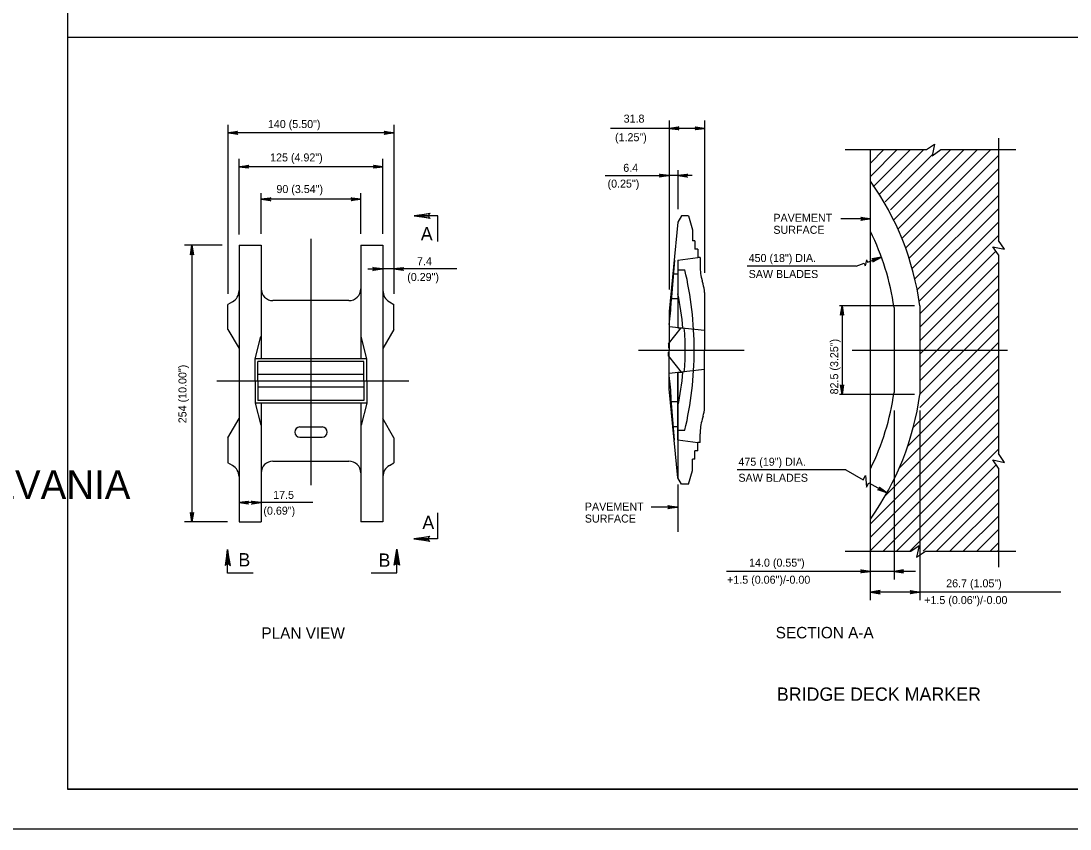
# Model space of a CAD drawing. Extents: x 639362 to 641108, y 298458 to 299646.
# Drawn here: x 640225.9 to 640619.2, y 298457.6 to 298760.6 of the extents above; entities that cross this region are included whole.
import ezdxf

# ---------------------------------------------------------------- set-up
doc = ezdxf.new("R2010")
doc.units = 0
for name, color, linetype in [('1', 7, 'Continuous'), ('2', 7, 'Continuous'), ('3', 7, 'Continuous'), ('PLT-BNDY', 7, 'Continuous')]:
    doc.layers.add(name, color=color, linetype=linetype)

# ---------------------------------------------------------------- blocks, each defined once
blk = doc.blocks.new('RARROW')
at = {"layer": '3'}
blk.add_lwpolyline([(-2.2695, 0.285), (-2.184875, 0.12075), (0, 0), (-2.2695, 0.285), (-2.38575, 0.384625), (0, 0), (-2.183125, -0.108), (-2.262875, -0.2705), (0, 0), (-2.38575, -0.379125), (-2.262875, -0.2705)], dxfattribs=at)

msp = doc.modelspace()

# ---------------------------------------------------------------- linework, layer by layer
at = {"layer": '1'}
for p, q in [((640243.31, 299036.63), (640243.31, 298472.63)), ((640243.31, 298754.63), (640829.31, 298754.63)), ((641029.31, 298472.63), (640243.31, 298472.63)), ((640243.31, 298472.63), (640829.31, 298472.63))]:
    msp.add_line(p, q, dxfattribs=at)
at = {"layer": '2'}
for p, q in [((640468.92, 298723.36), (640468.92, 298659.92)), ((640482.21, 298723.36), (640482.21, 298666.21)), ((640303.46, 298721.7), (640303.46, 298658.32)), ((640365.72, 298718.7), (640303.46, 298718.7)), ((640365.72, 298721.7), (640365.72, 298658.32)), ((640482.21, 298720.36), (640446.94, 298720.36)), ((640592.33, 298716.72), (640592.33, 298678.38)), ((640534.93, 298712.39), (640565.36, 298712.39)), ((640544.39, 298712.38), (640544.41, 298712.39)), ((640544.39, 298707.37), (640549.41, 298712.39)), ((640544.39, 298702.36), (640554.42, 298712.39)), ((640544.39, 298543.43), (640544.39, 298712.39)), ((640545.44, 298698.39), (640559.43, 298712.39)), ((640547.68, 298695.63), (640564.44, 298712.39)), ((640551.84, 298689.77), (640574.46, 298712.39)), ((640553.08, 298686), (640579.47, 298712.39)), ((640554.68, 298682.59), (640584.48, 298712.39)), ((640556.17, 298679.08), (640589.48, 298712.39)), ((640565.36, 298712.39), (640568.44, 298714.44)), ((640568.44, 298714.44), (640567.53, 298710.04)), ((640567.53, 298710.04), (640570.82, 298712.39)), ((640570.82, 298712.39), (640598.86, 298712.39)), ((640307.61, 298680.52), (640307.61, 298708.97)), ((640361.56, 298680.82), (640361.56, 298708.97)), ((640549.92, 298692.86), (640567.64, 298710.58)), ((640557.56, 298675.46), (640592.33, 298710.23)), ((640361.56, 298705.97), (640307.61, 298705.97)), ((640472.14, 298704.67), (640472.14, 298690.08)), ((640558.84, 298671.73), (640592.33, 298705.22)), ((640444.93, 298702.66), (640468.92, 298702.66)), ((640477.55, 298702.66), (640468.92, 298702.66)), ((640560, 298667.88), (640592.33, 298700.21)), ((640315.91, 298680.82), (640315.91, 298696.07)), ((640353.26, 298680.82), (640353.26, 298696.07)), ((640561.03, 298663.91), (640592.33, 298695.2)), ((640353.26, 298693.8), (640315.91, 298693.8)), ((640382.2, 298687.58), (640373.32, 298687.58)), ((640382.2, 298677.95), (640382.2, 298687.58)), ((640473.47, 298687.55), (640472.14, 298685.17)), ((640476.19, 298687.55), (640473.47, 298687.55)), ((640476.19, 298687.55), (640477.59, 298682.33)), ((640561.93, 298659.79), (640592.33, 298690.19)), ((640472.14, 298685.17), (640468.92, 298651.74)), ((640544.39, 298686.43), (640533.26, 298686.43)), ((640562.68, 298655.53), (640592.33, 298685.18)), ((640477.59, 298682.33), (640477.59, 298678.19)), ((640562.92, 298650.77), (640592.33, 298680.18)), ((640301.31, 298676.52), (640287.16, 298676.52)), ((640289.95, 298676.52), (640289.95, 298572.76)), ((640307.61, 298676.52), (640307.61, 298572.76)), ((640307.61, 298676.52), (640315.91, 298676.52)), ((640315.91, 298676.52), (640315.91, 298633.98)), ((640334.59, 298678.97), (640334.59, 298586.59)), ((640353.26, 298676.52), (640361.56, 298676.52)), ((640353.26, 298676.52), (640353.26, 298633.98)), ((640361.56, 298676.52), (640361.56, 298572.76)), ((640478.57, 298678.17), (640477.7, 298678.19)), ((640478.57, 298678.17), (640478.57, 298675.06)), ((640592.33, 298672.91), (640590.28, 298675.99)), ((640590.28, 298675.99), (640594.68, 298675.09)), ((640594.68, 298675.09), (640592.33, 298678.38)), ((640472.14, 298670.91), (640479.64, 298671.93)), ((640479.64, 298675.04), (640478.57, 298675.06)), ((640479.64, 298675.04), (640479.64, 298671.93)), ((640480.51, 298671.91), (640479.64, 298671.93)), ((640480.51, 298671.91), (640480.51, 298668.68)), ((640543.21, 298670.21), (640548.48, 298672.12)), ((640562.92, 298645.76), (640591.43, 298674.27)), ((640592.33, 298672.91), (640592.33, 298598.42)), ((640355.97, 298667.66), (640361.4, 298667.66)), ((640365.72, 298667.66), (640361.64, 298667.66)), ((640389.26, 298667.66), (640365.72, 298667.66)), ((640470.85, 298670.98), (640469.68, 298655.59)), ((640472.14, 298670.91), (640472.14, 298645.64)), ((640538.96, 298668.66), (640498.21, 298668.66)), ((640538.96, 298668.66), (640542.03, 298669.78)), ((640542.03, 298669.78), (640542.37, 298668.84)), ((640542.88, 298671.12), (640542.37, 298668.84)), ((640542.88, 298671.12), (640543.21, 298670.21)), ((640562.92, 298640.75), (640592.33, 298670.16)), ((640470.46, 298665.86), (640472.14, 298665.86)), ((640472.14, 298667.32), (640474.77, 298667.32)), ((640562.92, 298635.74), (640592.33, 298665.15)), ((640481.61, 298662.05), (640481.29, 298663.16)), ((640562.92, 298630.73), (640592.33, 298660.14)), ((640348.84, 298655.77), (640320.34, 298655.77)), ((640469.68, 298656.51), (640472.14, 298656.51)), ((640482.14, 298658.81), (640482.14, 298637.23)), ((640305.17, 298655.31), (640303.46, 298654.32)), ((640303.46, 298644.96), (640303.46, 298654.32)), ((640364, 298655.31), (640365.72, 298654.32)), ((640365.72, 298644.96), (640365.72, 298654.32)), ((640468.92, 298651.74), (640468.92, 298637.23)), ((640560.92, 298653.87), (640532.71, 298653.87)), ((640533.71, 298653.87), (640533.71, 298620.58)), ((640553.25, 298653.19), (640553.25, 298621.27)), ((640562.92, 298625.73), (640592.33, 298655.13)), ((640562.92, 298653.87), (640562.92, 298620.58)), ((640562.92, 298620.72), (640592.33, 298650.12)), ((640303.46, 298644.96), (640307.61, 298637.77)), ((640365.72, 298644.96), (640361.56, 298637.77)), ((640468.65, 298639.55), (640473.41, 298645.55)), ((640482.14, 298644.53), (640468.92, 298645.97)), ((640472.14, 298645.53), (640473.69, 298645.53)), ((640562.92, 298615.71), (640592.33, 298645.11)), ((640313.66, 298633.98), (640315.77, 298642.33)), ((640355.51, 298633.98), (640353.4, 298642.33)), ((640560.45, 298608.23), (640592.33, 298640.1)), ((640457.4, 298637.23), (640496.99, 298637.23)), ((640468.65, 298639.55), (640468.65, 298637.97)), ((640468.65, 298634.9), (640468.65, 298636.49)), ((640468.92, 298622.71), (640468.92, 298637.23)), ((640482.14, 298615.64), (640482.14, 298637.23)), ((640537.51, 298637.23), (640595.72, 298637.23)), ((640355.51, 298633.98), (640313.66, 298633.98)), ((640313.66, 298625.68), (640313.66, 298633.98)), ((640314.72, 298625.68), (640314.72, 298632.99)), ((640354.46, 298632.99), (640314.72, 298632.99)), ((640354.46, 298625.68), (640354.46, 298632.99)), ((640355.51, 298625.68), (640355.51, 298633.98)), ((640468.65, 298634.9), (640473.41, 298628.91)), ((640558.29, 298601.06), (640592.33, 298635.1)), ((640482.14, 298629.92), (640468.92, 298628.48)), ((640472.14, 298628.93), (640473.69, 298628.93)), ((640472.14, 298628.81), (640472.14, 298589.29)), ((640472.14, 298603.55), (640472.14, 298628.81)), ((640555.13, 298592.89), (640592.33, 298630.09)), ((640299.32, 298625.68), (640371.31, 298625.68)), ((640313.66, 298625.68), (640313.66, 298617.38)), ((640354.46, 298628.01), (640314.72, 298628.01)), ((640314.72, 298625.68), (640314.72, 298618.38)), ((640354.46, 298625.68), (640354.46, 298618.38)), ((640355.51, 298625.68), (640355.51, 298617.38)), ((640550.12, 298582.87), (640592.33, 298625.08)), ((640354.46, 298623.36), (640314.72, 298623.36)), ((640472.14, 298589.29), (640468.92, 298622.71)), ((640560.92, 298620.58), (640532.71, 298620.58)), ((640355.51, 298617.38), (640313.66, 298617.38)), ((640313.66, 298617.38), (640315.77, 298609.04)), ((640354.46, 298618.38), (640314.72, 298618.38)), ((640315.91, 298617.38), (640315.91, 298572.76)), ((640353.26, 298617.38), (640353.26, 298572.76)), ((640355.51, 298617.38), (640353.4, 298609.04)), ((640470.85, 298603.47), (640469.68, 298618.86)), ((640469.68, 298617.94), (640472.14, 298617.94)), ((640544.39, 298572.13), (640592.33, 298620.07)), ((640481.61, 298612.41), (640481.29, 298611.29)), ((640544.39, 298567.13), (640592.33, 298615.06)), ((640553.25, 298614.58), (640553.25, 298551.25)), ((640562.92, 298614.58), (640562.92, 298543.43)), ((640303.46, 298604.32), (640307.61, 298611.52)), ((640330.41, 298608.39), (640338.77, 298608.39)), ((640365.72, 298604.32), (640361.56, 298611.52)), ((640470.46, 298608.59), (640472.14, 298608.59)), ((640544.39, 298562.12), (640592.33, 298610.05)), ((640330.41, 298604.58), (640338.77, 298604.58)), ((640472.14, 298607.14), (640474.77, 298607.14)), ((640480.51, 298602.55), (640480.51, 298605.78)), ((640549.15, 298561.86), (640592.33, 298605.04)), ((640303.46, 298604.32), (640303.46, 298594.97)), ((640365.72, 298604.32), (640365.72, 298594.97)), ((640472.14, 298603.55), (640479.64, 298602.53)), ((640480.51, 298602.55), (640479.64, 298602.53)), ((640479.64, 298599.42), (640479.64, 298602.53)), ((640479.64, 298599.42), (640478.57, 298599.4)), ((640478.57, 298596.29), (640478.57, 298599.4)), ((640554.15, 298561.86), (640592.33, 298600.04)), ((640594.68, 298595.13), (640592.33, 298598.42)), ((640305.17, 298593.98), (640303.46, 298594.97)), ((640320.34, 298595.59), (640348.84, 298595.59)), ((640364, 298593.98), (640365.72, 298594.97)), ((640477.59, 298592.12), (640477.59, 298596.27)), ((640478.57, 298596.29), (640477.7, 298596.27)), ((640559.16, 298561.86), (640591.5, 298594.2)), ((640592.33, 298592.95), (640590.28, 298596.03)), ((640590.28, 298596.03), (640594.68, 298595.13)), ((640592.33, 298592.95), (640592.33, 298555.85)), ((640473.47, 298586.9), (640472.14, 298589.29)), ((640476.19, 298586.9), (640477.59, 298592.12)), ((640535.12, 298592.27), (640494.36, 298592.27)), ((640535.12, 298592.27), (640541.64, 298588.63)), ((640541.64, 298588.63), (640542.49, 298590.16)), ((640542.49, 298590.16), (640542.86, 298585.81)), ((640564.17, 298561.86), (640592.33, 298590.02)), ((640472.14, 298586.8), (640472.14, 298569.08)), ((640476.19, 298586.9), (640473.47, 298586.9)), ((640542.86, 298585.81), (640543.77, 298587.45)), ((640543.77, 298587.45), (640550.57, 298583.67)), ((640569.18, 298561.86), (640592.33, 298585.01)), ((640315.91, 298580.01), (640307.61, 298580.01)), ((640335.34, 298580.01), (640315.91, 298580.01)), ((640472.04, 298578.32), (640462.16, 298578.32)), ((640574.19, 298561.86), (640592.33, 298580)), ((640382.08, 298576.2), (640382.08, 298566.45)), ((640579.2, 298561.86), (640592.33, 298574.99)), ((640303.31, 298572.76), (640287.16, 298572.76)), ((640307.61, 298572.76), (640315.91, 298572.76)), ((640361.56, 298572.76), (640353.26, 298572.76)), ((640584.21, 298561.86), (640592.33, 298569.98)), ((640382.08, 298566.45), (640373.2, 298566.45)), ((640303.35, 298553.53), (640303.35, 298562.4)), ((640366.8, 298553.68), (640366.8, 298562.56)), ((640534.93, 298561.86), (640559.51, 298561.86)), ((640559.51, 298561.86), (640562.59, 298563.91)), ((640562.59, 298563.91), (640561.68, 298559.51)), ((640561.68, 298559.51), (640564.97, 298561.86)), ((640564.97, 298561.86), (640598.86, 298561.86)), ((640589.21, 298561.86), (640592.33, 298564.98)), ((640591.97, 298561.86), (640592.33, 298562.18)), ((640312.97, 298553.53), (640303.35, 298553.53)), ((640357.17, 298553.68), (640366.8, 298553.68)), ((640553.25, 298554.25), (640490.35, 298554.25)), ((640561.32, 298554.25), (640553.25, 298554.25)), ((640562.92, 298546.43), (640544.39, 298546.43)), ((640615.75, 298546.43), (640562.92, 298546.43))]:
    msp.add_line(p, q, dxfattribs=at)
for points in [[(640306.86, 298718.27), (640306.74, 298718.52), (640303.46, 298718.7), (640306.86, 298718.27), (640307.04, 298718.12), (640303.46, 298718.7), (640306.73, 298718.86), (640306.85, 298719.1), (640303.46, 298718.7), (640307.04, 298719.27), (640306.85, 298719.1)], [(640362.31, 298719.12), (640362.44, 298718.88), (640365.72, 298718.7), (640362.31, 298719.12), (640362.14, 298719.27), (640365.72, 298718.7), (640362.44, 298718.53), (640362.32, 298718.29), (640365.72, 298718.7), (640362.14, 298718.13), (640362.32, 298718.29)], [(640472.32, 298719.93), (640472.2, 298720.18), (640468.92, 298720.36), (640472.32, 298719.93), (640472.5, 298719.78), (640468.92, 298720.36), (640472.19, 298720.52), (640472.31, 298720.76), (640468.92, 298720.36), (640472.5, 298720.93), (640472.31, 298720.76)], [(640478.8, 298720.79), (640478.93, 298720.54), (640482.21, 298720.36), (640478.8, 298720.79), (640478.63, 298720.93), (640482.21, 298720.36), (640478.93, 298720.19), (640478.81, 298719.95), (640482.21, 298720.36), (640478.63, 298719.79), (640478.81, 298719.95)], [(640311.01, 298705.54), (640310.89, 298705.79), (640307.61, 298705.97), (640311.01, 298705.54), (640311.19, 298705.39), (640307.61, 298705.97), (640310.88, 298706.13), (640311, 298706.38), (640307.61, 298705.97), (640311.19, 298706.54), (640311, 298706.38)], [(640358.16, 298706.4), (640358.29, 298706.15), (640361.56, 298705.97), (640358.16, 298706.4), (640357.98, 298706.54), (640361.56, 298705.97), (640358.29, 298705.81), (640358.17, 298705.56), (640361.56, 298705.97), (640357.98, 298705.4), (640358.17, 298705.56)], [(640465.51, 298703.09), (640465.64, 298702.85), (640468.92, 298702.66), (640465.51, 298703.09), (640465.34, 298703.24), (640468.92, 298702.66), (640465.64, 298702.5), (640465.52, 298702.26), (640468.92, 298702.66), (640465.34, 298702.1), (640465.52, 298702.26)], [(640475.55, 298702.23), (640475.42, 298702.48), (640472.14, 298702.66), (640475.55, 298702.23), (640475.73, 298702.08), (640472.14, 298702.66), (640475.42, 298702.82), (640475.54, 298703.07), (640472.14, 298702.66), (640475.73, 298703.23), (640475.54, 298703.07)], [(640319.32, 298693.37), (640319.19, 298693.62), (640315.91, 298693.8), (640319.32, 298693.37), (640319.49, 298693.22), (640315.91, 298693.8), (640319.19, 298693.96), (640319.3, 298694.2), (640315.91, 298693.8), (640319.49, 298694.37), (640319.3, 298694.2)], [(640349.86, 298694.22), (640349.99, 298693.98), (640353.26, 298693.8), (640349.86, 298694.22), (640349.68, 298694.37), (640353.26, 298693.8), (640349.99, 298693.63), (640349.87, 298693.39), (640353.26, 298693.8), (640349.68, 298693.23), (640349.87, 298693.39)], [(640540.99, 298686.86), (640541.11, 298686.61), (640544.39, 298686.43), (640540.99, 298686.86), (640540.81, 298687.01), (640544.39, 298686.43), (640541.12, 298686.26), (640541, 298686.02), (640544.39, 298686.43), (640540.81, 298685.86), (640541, 298686.02)], [(640289.52, 298673.12), (640289.77, 298673.24), (640289.95, 298676.52), (640289.52, 298673.12), (640289.38, 298672.94), (640289.95, 298676.52), (640290.12, 298673.25), (640290.36, 298673.13), (640289.95, 298676.52), (640290.52, 298672.94), (640290.36, 298673.13)], [(640545.41, 298670.58), (640545.45, 298670.85), (640548.48, 298672.12), (640545.41, 298670.58), (640545.3, 298670.38), (640548.48, 298672.12), (640545.34, 298671.18), (640545.14, 298671.37), (640548.48, 298672.12), (640544.92, 298671.46), (640545.14, 298671.37)], [(640358, 298668.08), (640358.12, 298667.84), (640361.4, 298667.66), (640358, 298668.08), (640357.82, 298668.23), (640361.4, 298667.66), (640358.13, 298667.49), (640358.01, 298667.25), (640361.4, 298667.66), (640357.82, 298667.09), (640358.01, 298667.25)], [(640369.12, 298667.23), (640369, 298667.48), (640365.72, 298667.66), (640369.12, 298667.23), (640369.3, 298667.08), (640365.72, 298667.66), (640368.99, 298667.82), (640369.11, 298668.06), (640365.72, 298667.66), (640369.3, 298668.23), (640369.11, 298668.06)], [(640533.28, 298650.46), (640533.53, 298650.59), (640533.71, 298653.87), (640533.28, 298650.46), (640533.13, 298650.29), (640533.71, 298653.87), (640533.87, 298650.6), (640534.11, 298650.48), (640533.71, 298653.87), (640534.28, 298650.29), (640534.11, 298650.48)], [(640534.14, 298623.99), (640533.89, 298623.86), (640533.71, 298620.58), (640534.14, 298623.99), (640534.29, 298624.16), (640533.71, 298620.58), (640533.54, 298623.86), (640533.3, 298623.98), (640533.71, 298620.58), (640533.14, 298624.16), (640533.3, 298623.98)], [(640547.77, 298585.66), (640547.77, 298585.39), (640550.57, 298583.67), (640547.77, 298585.66), (640547.69, 298585.87), (640550.57, 298583.67), (640547.6, 298585.08), (640547.38, 298584.92), (640550.57, 298583.67), (640547.15, 298584.87), (640547.38, 298584.92)], [(640311.01, 298579.58), (640310.89, 298579.83), (640307.61, 298580.01), (640311.01, 298579.58), (640311.19, 298579.43), (640307.61, 298580.01), (640310.89, 298580.17), (640311, 298580.42), (640307.61, 298580.01), (640311.19, 298580.58), (640311, 298580.42)], [(640312.51, 298580.44), (640312.63, 298580.19), (640315.91, 298580.01), (640312.51, 298580.44), (640312.33, 298580.59), (640315.91, 298580.01), (640312.64, 298579.85), (640312.52, 298579.61), (640315.91, 298580.01), (640312.33, 298579.44), (640312.52, 298579.61)], [(640468.63, 298578.75), (640468.76, 298578.5), (640472.04, 298578.32), (640468.63, 298578.75), (640468.46, 298578.9), (640472.04, 298578.32), (640468.76, 298578.16), (640468.64, 298577.91), (640472.04, 298578.32), (640468.46, 298577.75), (640468.64, 298577.91)], [(640290.38, 298576.17), (640290.13, 298576.04), (640289.95, 298572.76), (640290.38, 298576.17), (640290.53, 298576.34), (640289.95, 298572.76), (640289.79, 298576.04), (640289.55, 298576.16), (640289.95, 298572.76), (640289.38, 298576.34), (640289.55, 298576.16)], [(640540.99, 298554.68), (640541.12, 298554.43), (640544.39, 298554.25), (640540.99, 298554.68), (640540.81, 298554.83), (640544.39, 298554.25), (640541.12, 298554.09), (640541, 298553.85), (640544.39, 298554.25), (640540.81, 298553.68), (640541, 298553.85)], [(640556.65, 298554.68), (640556.52, 298554.43), (640553.25, 298554.25), (640556.65, 298554.68), (640556.83, 298554.83), (640553.25, 298554.25), (640556.52, 298554.09), (640556.64, 298553.85), (640553.25, 298554.25), (640556.83, 298553.68), (640556.64, 298553.85)], [(640547.8, 298546.86), (640547.67, 298546.61), (640544.39, 298546.43), (640547.8, 298546.86), (640547.97, 298547.01), (640544.39, 298546.43), (640547.67, 298546.27), (640547.79, 298546.03), (640544.39, 298546.43), (640547.97, 298545.86), (640547.79, 298546.03)], [(640559.52, 298546.86), (640559.65, 298546.61), (640562.92, 298546.43), (640559.52, 298546.86), (640559.34, 298547.01), (640562.92, 298546.43), (640559.65, 298546.27), (640559.53, 298546.03), (640562.92, 298546.43), (640559.34, 298545.86), (640559.53, 298546.03)]]:
    msp.add_lwpolyline(points, dxfattribs=at)
for centre, radius, start, end in [((640458.11, 298639.32), 105.82, 7.9054, 35.3742), ((640458.11, 298639.32), 96.14, 8.2945, 26.1755), ((640500.51, 298668.68), 20, 180, 196.0037), ((640302.74, 298659.52), 4.87, 300.0116, 0), ((640320.34, 298660.2), 4.43, 180, 270), ((640348.83, 298660.2), 4.43, 270, 0), ((640366.43, 298659.53), 4.87, 180, 239.9911), ((640472.14, 298658.81), 10, 0, 18.8675), ((640372.27, 298636.71), 102.18, 4.9359, 12.1966), ((640372.27, 298636.71), 102.68, 0.2899, 4.891), ((640372.27, 298637.75), 102.68, 355.109, 359.7101), ((640372.27, 298637.75), 102.18, 347.8034, 355.0641), ((640458.11, 298635.14), 96.14, 333.8245, 351.7055), ((640458.11, 298635.14), 105.82, 324.6258, 352.0946), ((640472.14, 298615.64), 10, 341.1325, 0), ((640330.41, 298606.49), 1.91, 90, 270), ((640338.77, 298606.49), 1.91, 270, 90), ((640500.51, 298605.78), 20, 163.9963, 180), ((640302.74, 298589.76), 4.87, 0, 59.9884), ((640320.34, 298591.16), 4.43, 90, 180), ((640348.83, 298591.16), 4.43, 0, 90), ((640366.43, 298589.76), 4.87, 120.0089, 180)]:
    msp.add_arc(centre, radius, start, end, dxfattribs=at)
for centre, major_axis, ratio, start_param, end_param in [((640392.23, 298637.23), (0, -106.68), 0.806534, 1.570813, 1.856752), ((640458.96, 298657.48), (0, -28.55), 0.376297, 1.186589, 1.504441), ((640392.23, 298637.23), (0, 106.68), 0.806534, 4.426434, 4.712372), ((640458.96, 298616.97), (0, 28.55), 0.376297, 4.778744, 5.096596)]:
    msp.add_ellipse(centre, major_axis=major_axis, ratio=ratio, start_param=start_param, end_param=end_param, dxfattribs=at)
at = {"layer": 'PLT-BNDY'}
msp.add_lwpolyline([(640203.31, 299051.63), (641044.31, 299051.63), (641044.31, 298457.63), (640203.31, 298457.63)], close=True, dxfattribs=at)

# ---------------------------------------------------------------- block references
at = {"layer": '2', "xscale": 2.5148695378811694}
for p, yscale, rotation in [((640373.32, 298687.58), 2.618592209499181, 180), ((640373.2, 298566.45), 2.618592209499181, 180), ((640303.35, 298562.4), -2.618592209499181, 90.00000000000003), ((640366.8, 298562.56), 2.618592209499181, 89.99999999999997)]:
    msp.add_blockref('RARROW', p, dxfattribs=dict(at, yscale=yscale, rotation=rotation))

# ---------------------------------------------------------------- texts
at = {"layer": '1'}
msp.add_text('COMMONWEALTH OF PENNSYLVANIA', height=10.7828, dxfattribs=at).set_placement((640000.9, 298581.36))
at = {"layer": '2'}
for s, height, p in [('140 (5.50")', 3, (640318.44, 298720.49)), ('31.8', 3, (640451.83, 298722.53)), ('(1.25")', 3, (640448.6, 298715.56)), ('125 (4.92")', 3, (640319.28, 298707.97)), ('6.4', 3, (640451.69, 298704.08)), ('90 (3.54")', 3, (640321.64, 298696.11)), ('(0.25")', 3, (640445.8, 298698.15)), ('PAVEMENT', 3, (640507.98, 298685.33)), ('A', 5, (640375.77, 298678.35)), ('SURFACE', 3, (640507.98, 298680.83)), ('7.4', 3, (640374.35, 298669.07)), ('450 (18") DIA.', 3, (640498.71, 298670.26)), ('(0.29")', 3, (640370.68, 298663.14)), ('SAW BLADES', 3, (640498.71, 298664.26)), ('475 (19") DIA.', 3, (640494.88, 298593.85)), ('SAW BLADES', 3, (640494.88, 298587.85)), ('17.5', 3, (640320.42, 298581.43)), ('(0.69")', 3, (640316.76, 298575.5)), ('PAVEMENT', 3, (640437.28, 298577.05)), ('A', 5, (640376.35, 298570.08)), ('SURFACE', 3, (640437.28, 298572.55)), ('B', 5, (640307.37, 298556.1)), ('B', 5, (640359.92, 298555.95)), ('14.0 (0.55")', 3, (640498.87, 298556.01)), ('+1.5 (0.06")/-0.00', 3, (640490.62, 298549.62)), ('26.7 (1.05")', 3, (640572.78, 298548.27)), ('+1.5 (0.06")/-0.00', 3, (640564.54, 298541.98)), ('PLAN VIEW', 4.3, (640316, 298528.96)), ('SECTION A-A', 4.3, (640508.85, 298529.12)), ('BRIDGE DECK MARKER', 5, (640509.27, 298505.71))]:
    msp.add_text(s, height=height, dxfattribs=at).set_placement(p)
for s, p in [('82.5 (3.25")', (640532.29, 298620.61)), ('254 (10.00")', (640287.9, 298609.79))]:
    msp.add_text(s, height=3, rotation=90, dxfattribs=at).set_placement(p)

doc.saveas('drawing.dxf')
